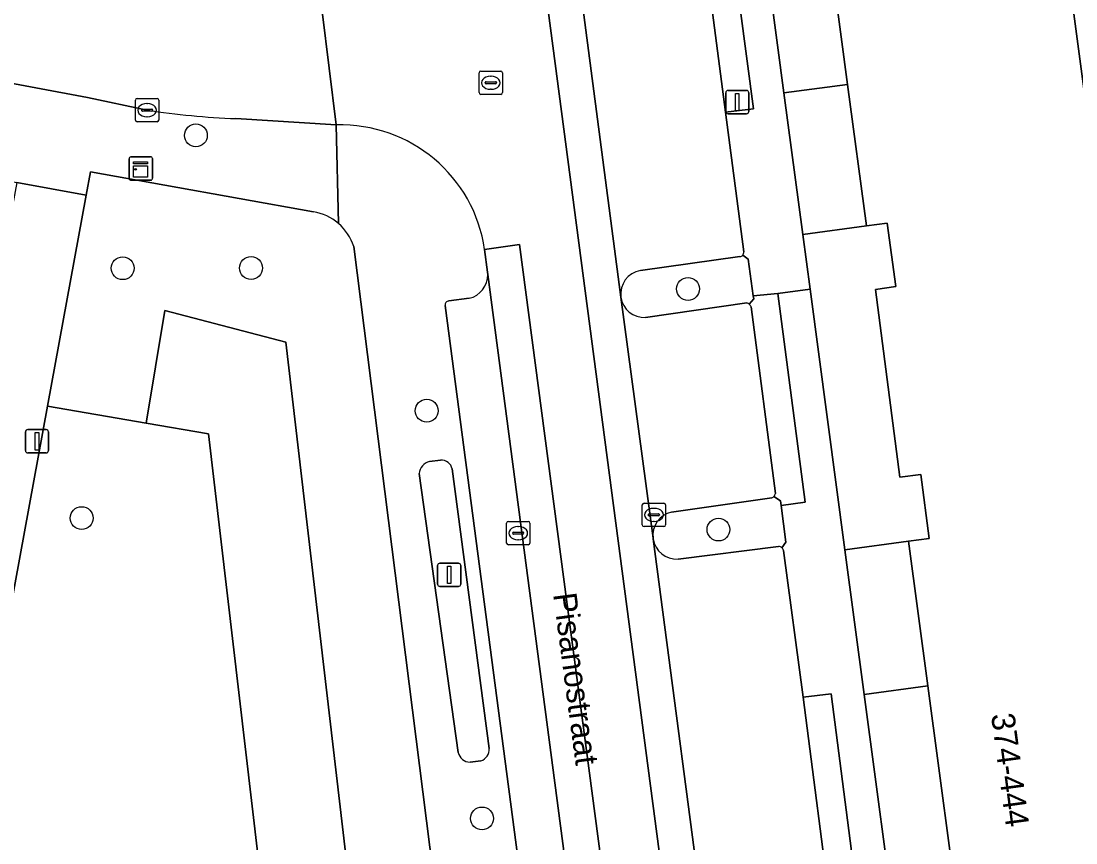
# Model space of a CAD drawing. Extents: x 160554 to 161248, y 385329 to 386506.
# Drawn here: x 161065.87 to 161111.05, y 385894.19 to 385929.39 of the extents above; entities that cross this region are included whole.
import ezdxf

# ---------------------------------------------------------------- set-up
doc = ezdxf.new("R2010")
doc.units = 0
for name, color, linetype in [('IMGEO_Boom', 7, 'Continuous'), ('IMGEO_Groenvoorziening', 7, 'Continuous'), ('IMGEO_Haag', 7, 'Continuous'), ('IMGEO_Kast', 7, 'Continuous'), ('IMGEO_Kolk', 7, 'Continuous'), ('IMGEO_Lichtmast', 7, 'Continuous'), ('IMGEO_Openbare_ruimte_label', 7, 'Continuous'), ('IMGEO_Pand', 7, 'Continuous'), ('IMGEO_Pand_nummerreeks', 7, 'Continuous'), ('IMGEO_Parkeervlak_open', 7, 'Continuous'), ('IMGEO_Rijbaan_lokaal_gesloten', 7, 'Continuous'), ('IMGEO_Rijbaan_lokaal_open', 7, 'Continuous'), ('IMGEO_Rioolput', 7, 'Continuous'), ('IMGEO_Voetpad_open', 7, 'Continuous')]:
    doc.layers.add(name, color=color, linetype=linetype)

msp = doc.modelspace()

# ---------------------------------------------------------------- linework, layer by layer
at = {"layer": 'IMGEO_Boom'}
for centre in [(161073.358, 385924.495), (161070.224, 385918.805), (161075.721, 385918.814), (161094.439, 385917.918), (161083.247, 385912.7), (161068.466, 385908.101), (161095.744, 385907.61), (161085.615, 385895.235)]:
    msp.add_circle(centre, 0.489, dxfattribs=at)
at = {"layer": 'IMGEO_Groenvoorziening'}
for points in [[(161098.548, 385926.313), (161099.356, 385920.254), (161102.083, 385920.618), (161101.275, 385926.677)], [(161079.757, 385878.995), (161080.853, 385884.49), (161077.206, 385915.641), (161072.024, 385916.988), (161071.224, 385912.172), (161073.9, 385911.717), (161077.071, 385884.684), (161075.036, 385880.979), (161079.44, 385879.028)], [(161101.158, 385906.745), (161101.984, 385900.55), (161104.711, 385900.914), (161103.885, 385907.108)]]:
    msp.add_lwpolyline(points, close=True, dxfattribs=at)
for points in [[(161078.39, 385921.217), (161068.84, 385922.94), (161068.656, 385921.934), (161067, 385912.891), (161071.224, 385912.172), (161072.024, 385916.988), (161077.206, 385915.641), (161080.853, 385884.49), (161079.757, 385878.995), (161081.825, 385878.782), (161085.275, 385879.091), (161085.004, 385881.132), (161080.12, 385919.735)], [(161096.664, 385919.302), (161092.398, 385918.707)], [(161097.057, 385917.265), (161097.256, 385917.492), (161097.237, 385917.622), (161097.009, 385919.191), (161096.784, 385919.367)], [(161092.623, 385916.697), (161096.955, 385917.319)], [(161073.9, 385911.717), (161071.224, 385912.172), (161067, 385912.891), (161058.528, 385866.63), (161058.312, 385865.35)], [(161086.501, 385869.656), (161086.193, 385872.192), (161085.275, 385879.091), (161081.825, 385878.782), (161079.757, 385878.995), (161079.44, 385879.028), (161075.036, 385880.979), (161077.071, 385884.684), (161073.9, 385911.717)], [(161083.842, 385910.589), (161083.366, 385910.52)], [(161085.921, 385898.228), (161084.342, 385910.204)], [(161082.922, 385910.009), (161084.595, 385898.064)], [(161098.031, 385908.963), (161093.738, 385908.356)], [(161098.427, 385908.647), (161098.403, 385908.839), (161098.122, 385909.031)], [(161098.463, 385906.833), (161098.628, 385907.063), (161098.427, 385908.647)], [(161092.941, 385907.237), (161092.944, 385907.216)], [(161094.014, 385906.347), (161098.315, 385906.888)], [(161085.103, 385897.643), (161085.566, 385897.703)]]:
    msp.add_lwpolyline(points, dxfattribs=at)
for centre, radius, start, end in [((161078.046, 385919.066), 2.179, 49.4084, 80.9263), ((161078.045, 385919.064), 2.181, 17.9184, 49.408), ((161096.642, 385919.487), 0.186, 276.9194, 319.9665), ((161092.59, 385917.687), 1.038, 100.6546, 186.6899), ((161092.561, 385917.706), 1.011, 187.9847, 273.5363), ((161096.874, 385917.042), 0.289, 50.579, 73.6265), ((161083.513, 385909.944), 0.595, 104.3435, 173.6827), ((161083.85, 385910.082), 0.507, 13.9246, 90.8829), ((161097.92, 385909.206), 0.267, 294.5087, 319.0293), ((161093.951, 385907.361), 1.018, 102.0884, 186.9914), ((161093.958, 385907.371), 1.025, 188.6804, 273.1561), ((161098.321, 385906.677), 0.211, 47.6298, 91.5979), ((161085.113, 385898.172), 0.529, 191.7526, 268.9476), ((161085.405, 385898.194), 0.517, 288.1091, 3.7585)]:
    msp.add_arc(centre, radius, start, end, dxfattribs=at)
at = {"layer": 'IMGEO_Haag'}
for points in [[(161098.548, 385926.313), (161099.356, 385920.254), (161102.083, 385920.618), (161101.275, 385926.677)], [(161101.158, 385906.745), (161101.984, 385900.55), (161104.711, 385900.914), (161103.885, 385907.108)]]:
    msp.add_lwpolyline(points, close=True, dxfattribs=at)
at = {"layer": 'IMGEO_Kast'}
for p, q in [((161070.498, 385922.651), (161070.498, 385923.492)), ((161070.498, 385923.492), (161070.498, 385922.651)), ((161070.573, 385923.576), (161071.414, 385923.576)), ((161071.414, 385923.576), (161070.573, 385923.576)), ((161071.498, 385923.501), (161071.498, 385922.66)), ((161071.498, 385922.66), (161071.498, 385923.501)), ((161071.423, 385922.576), (161070.582, 385922.576)), ((161070.582, 385922.576), (161071.423, 385922.576))]:
    msp.add_line(p, q, dxfattribs=at)
for points in [[(161070.693, 385923.366), (161071.293, 385923.366), (161071.293, 385923.281), (161070.693, 385923.281), (161070.693, 385923.366)], [(161070.693, 385923.191), (161071.293, 385923.191), (161071.293, 385922.702), (161070.693, 385922.702), (161070.693, 385923.191)]]:
    msp.add_lwpolyline(points, dxfattribs=at)
msp.add_circle((161070.777, 385923.04), 0.0377, dxfattribs=at)
for centre, start, end in [((161070.576, 385923.498), 92.4484, 184.2845), ((161070.576, 385923.498), 92.4484, 184.2845), ((161071.42, 385923.498), 2.4484, 94.2845), ((161071.42, 385923.498), 2.4484, 94.2845), ((161070.576, 385922.654), 182.4484, 274.2845), ((161070.576, 385922.654), 182.4484, 274.2845), ((161071.42, 385922.654), 272.4484, 4.2845), ((161071.42, 385922.654), 272.4484, 4.2845)]:
    msp.add_arc(centre, 0.0779, start, end, dxfattribs=at)
at = {"layer": 'IMGEO_Kolk'}
for p, q in [((161070.767, 385925.151), (161070.767, 385926.003)), ((161070.842, 385926.077), (161071.694, 385926.077)), ((161071.768, 385926.003), (161071.768, 385925.151)), ((161071.026, 385925.571), (161071.026, 385925.583)), ((161071.464, 385925.534), (161071.066, 385925.534)), ((161071.069, 385925.62), (161071.467, 385925.62)), ((161071.255, 385925.857), (161071.28, 385925.857)), ((161071.51, 385925.583), (161071.51, 385925.571)), ((161071.694, 385925.077), (161070.842, 385925.077)), ((161071.278, 385925.297), (161071.253, 385925.297)), ((161092.555, 385908.739), (161093.407, 385908.739)), ((161092.48, 385907.813), (161092.48, 385908.665)), ((161092.782, 385908.282), (161093.18, 385908.282)), ((161092.968, 385908.519), (161092.993, 385908.519)), ((161093.481, 385908.665), (161093.481, 385907.813)), ((161086.668, 385907.03), (161086.668, 385907.882)), ((161086.743, 385907.956), (161087.595, 385907.956)), ((161087.669, 385907.882), (161087.669, 385907.03)), ((161092.739, 385908.233), (161092.739, 385908.245)), ((161093.177, 385908.196), (161092.779, 385908.196)), ((161092.991, 385907.959), (161092.966, 385907.959)), ((161093.223, 385908.245), (161093.223, 385908.233)), ((161086.927, 385907.45), (161086.927, 385907.462)), ((161087.365, 385907.413), (161086.967, 385907.413)), ((161086.97, 385907.499), (161087.368, 385907.499)), ((161087.156, 385907.736), (161087.181, 385907.736)), ((161087.411, 385907.462), (161087.411, 385907.45)), ((161093.407, 385907.739), (161092.555, 385907.739)), ((161087.595, 385906.956), (161086.743, 385906.956)), ((161087.179, 385907.176), (161087.154, 385907.176))]:
    msp.add_line(p, q, dxfattribs=at)
for points in [[(161070.767, 385925.151), (161070.767, 385926.003)], [(161070.842, 385926.077), (161071.694, 385926.077)], [(161071.768, 385926.003), (161071.768, 385925.151)], [(161071.694, 385925.077), (161070.842, 385925.077)], [(161092.555, 385908.739), (161093.407, 385908.739)], [(161092.48, 385907.813), (161092.48, 385908.665)], [(161093.481, 385908.665), (161093.481, 385907.813)], [(161086.668, 385907.03), (161086.668, 385907.882)], [(161086.743, 385907.956), (161087.595, 385907.956)], [(161087.669, 385907.882), (161087.669, 385907.03)], [(161093.407, 385907.739), (161092.555, 385907.739)], [(161087.595, 385906.956), (161086.743, 385906.956)]]:
    msp.add_lwpolyline(points, dxfattribs=at)
for centre, radius, start, end in [((161070.844, 385926.001), 0.0765, 91.552, 178.448), ((161070.844, 385926.001), 0.0765, 91.552, 178.448), ((161071.692, 385926.001), 0.0765, 1.552, 88.448), ((161071.692, 385926.001), 0.0765, 1.552, 88.448), ((161071.066, 385925.58), 0.0403, 85.8775, 175.7526), ((161071.063, 385925.57), 0.0366, 178.938, 274.7102), ((161071.467, 385925.577), 0.043, 264.8664, 352.4533), ((161071.471, 385925.582), 0.0386, 1.7309, 96.639), ((161070.844, 385925.153), 0.0765, 181.552, 268.448), ((161070.844, 385925.153), 0.0765, 181.552, 268.448), ((161071.692, 385925.153), 0.0765, 271.552, 358.448), ((161071.692, 385925.153), 0.0765, 271.552, 358.448), ((161092.557, 385908.663), 0.0765, 91.552, 178.448), ((161092.557, 385908.663), 0.0765, 91.552, 178.448), ((161093.405, 385908.663), 0.0765, 1.552, 88.448), ((161093.405, 385908.663), 0.0765, 1.552, 88.448), ((161092.779, 385908.242), 0.0403, 85.8775, 175.7526), ((161093.184, 385908.244), 0.0386, 1.7309, 96.639), ((161086.745, 385907.88), 0.0765, 91.552, 178.448), ((161086.745, 385907.88), 0.0765, 91.552, 178.448), ((161087.593, 385907.88), 0.0765, 1.552, 88.448), ((161087.593, 385907.88), 0.0765, 1.552, 88.448), ((161092.557, 385907.815), 0.0765, 181.552, 268.448), ((161092.557, 385907.815), 0.0765, 181.552, 268.448), ((161092.776, 385908.232), 0.0366, 178.938, 274.7102), ((161093.18, 385908.239), 0.043, 264.8664, 352.4533), ((161093.405, 385907.815), 0.0765, 271.552, 358.448), ((161093.405, 385907.815), 0.0765, 271.552, 358.448), ((161086.967, 385907.459), 0.0403, 85.8775, 175.7526), ((161086.964, 385907.449), 0.0366, 178.938, 274.7102), ((161087.368, 385907.456), 0.043, 264.8664, 352.4533), ((161087.372, 385907.461), 0.0386, 1.7309, 96.639), ((161086.745, 385907.032), 0.0765, 181.552, 268.448), ((161086.745, 385907.032), 0.0765, 181.552, 268.448), ((161087.593, 385907.032), 0.0765, 271.552, 358.448), ((161087.593, 385907.032), 0.0765, 271.552, 358.448)]:
    msp.add_arc(centre, radius, start, end, dxfattribs=at)
for centre, major_axis, ratio, start_param, end_param in [((161071.254, 385925.577), (-0.387, 0.002), 0.722429, 4.712389, 7.853982), ((161071.279, 385925.577), (-0.39, 0.002), 0.717154, 1.570796, 4.712389), ((161092.967, 385908.239), (-0.387, 0.002), 0.722429, 4.712389, 7.853982), ((161092.992, 385908.239), (-0.39, 0.002), 0.717154, 1.570796, 4.712389), ((161087.155, 385907.456), (-0.387, 0.002), 0.722429, 4.712389, 7.853982), ((161087.18, 385907.456), (-0.39, 0.002), 0.717154, 1.570796, 4.712389)]:
    msp.add_ellipse(centre, major_axis=major_axis, ratio=ratio, start_param=start_param, end_param=end_param, dxfattribs=at)
at = {"layer": 'IMGEO_Lichtmast'}
for p, q in [((161096.153, 385926.421), (161096.943, 385926.421)), ((161096.943, 385926.421), (161096.153, 385926.421)), ((161096.053, 385925.521), (161096.053, 385926.321)), ((161096.053, 385926.321), (161096.053, 385925.521)), ((161097.043, 385926.321), (161097.043, 385925.521)), ((161097.043, 385925.521), (161097.043, 385926.321)), ((161096.943, 385925.421), (161096.153, 385925.421)), ((161096.153, 385925.421), (161096.943, 385925.421)), ((161066.156, 385911.892), (161066.946, 385911.892)), ((161066.946, 385911.892), (161066.156, 385911.892)), ((161066.056, 385910.992), (161066.056, 385911.792)), ((161066.056, 385911.792), (161066.056, 385910.992)), ((161067.046, 385911.792), (161067.046, 385910.992)), ((161067.046, 385910.992), (161067.046, 385911.792)), ((161066.946, 385910.892), (161066.156, 385910.892)), ((161066.156, 385910.892), (161066.946, 385910.892)), ((161083.712, 385905.27), (161083.712, 385906.07)), ((161083.712, 385906.07), (161083.712, 385905.27)), ((161083.812, 385906.17), (161084.602, 385906.17)), ((161084.602, 385906.17), (161083.812, 385906.17)), ((161084.702, 385906.07), (161084.702, 385905.27)), ((161084.702, 385905.27), (161084.702, 385906.07)), ((161084.602, 385905.17), (161083.812, 385905.17)), ((161083.812, 385905.17), (161084.602, 385905.17))]:
    msp.add_line(p, q, dxfattribs=at)
for points in [[(161096.473, 385926.296), (161096.623, 385926.296), (161096.623, 385925.546), (161096.473, 385925.546), (161096.473, 385926.296)], [(161066.476, 385911.767), (161066.626, 385911.767), (161066.626, 385911.017), (161066.476, 385911.017), (161066.476, 385911.767)], [(161084.132, 385906.045), (161084.282, 385906.045), (161084.282, 385905.295), (161084.132, 385905.295), (161084.132, 385906.045)]]:
    msp.add_lwpolyline(points, dxfattribs=at)
for centre, start, end in [((161096.153, 385926.321), 90, 180), ((161096.153, 385926.321), 90, 180), ((161096.943, 385926.321), 0, 90), ((161096.943, 385926.321), 360, 90), ((161096.153, 385925.521), 180, 270), ((161096.153, 385925.521), 180, 270), ((161096.943, 385925.521), 270, 0), ((161096.943, 385925.521), 270, 0), ((161066.156, 385911.792), 90, 180), ((161066.156, 385911.792), 90, 180), ((161066.946, 385911.792), 0, 90), ((161066.946, 385911.792), 360, 90), ((161066.156, 385910.992), 180, 270), ((161066.156, 385910.992), 180, 270), ((161066.946, 385910.992), 270, 0), ((161066.946, 385910.992), 270, 0), ((161083.812, 385906.07), 90, 180), ((161083.812, 385906.07), 90, 180), ((161084.602, 385906.07), 0, 90), ((161084.602, 385906.07), 360, 90), ((161083.812, 385905.27), 180, 270), ((161083.812, 385905.27), 180, 270), ((161084.602, 385905.27), 270, 0), ((161084.602, 385905.27), 270, 0)]:
    msp.add_arc(centre, 0.1, start, end, dxfattribs=at)
at = {"layer": 'IMGEO_Pand'}
for points in [[(161122.665, 385842.019), (161108.009, 385951.88)], [(161099.853, 385937.33), (161101.275, 385926.677), (161102.083, 385920.618), (161102.974, 385920.737), (161103.337, 385918.015), (161102.464, 385917.898), (161103.519, 385909.85), (161104.41, 385909.969), (161104.776, 385907.227), (161103.885, 385907.108), (161104.711, 385900.914), (161106.152, 385890.116), (161106.955, 385884.097), (161107.846, 385884.216), (161108.209, 385881.494), (161107.318, 385881.375), (161108.383, 385873.388), (161109.274, 385873.507), (161109.637, 385870.785)]]:
    msp.add_lwpolyline(points, dxfattribs=at)
at = {"layer": 'IMGEO_Parkeervlak_open'}
for points in [[(161088.129, 385943.731), (161091.559, 385917.566)], [(161096.829, 385919.511), (161096.047, 385925.489), (161094.628, 385936.338)], [(161092.398, 385918.707), (161096.664, 385919.302)], [(161091.601, 385874.985), (161085.861, 385918.538)], [(161085.06, 385917.516), (161084.195, 385917.403)], [(161091.559, 385917.566), (161092.941, 385907.237)], [(161096.955, 385917.319), (161092.623, 385916.697)], [(161084.034, 385917.203), (161089.495, 385875.772)], [(161098.183, 385909.158), (161097.143, 385917.154)], [(161093.738, 385908.356), (161098.031, 385908.963)], [(161092.944, 385907.216), (161095.353, 385888.901)], [(161098.315, 385906.888), (161094.014, 385906.347)], [(161100.62, 385890.798), (161099.365, 385900.431), (161098.527, 385906.718)]]:
    msp.add_lwpolyline(points, dxfattribs=at)
for centre, radius, start, end in [((161096.642, 385919.487), 0.186, 276.9194, 319.9665), ((161096.637, 385919.492), 0.193, 319.6683, 5.6236), ((161092.59, 385917.687), 1.038, 100.6546, 186.6899), ((161084.831, 385918.521), 1.031, 282.8629, 0.9614), ((161084.202, 385917.232), 0.171, 92.4059, 189.926), ((161092.561, 385917.706), 1.011, 187.9847, 273.5363), ((161096.874, 385917.042), 0.289, 50.579, 73.6265), ((161096.885, 385917.043), 0.281, 23.3152, 52.22), ((161097.92, 385909.206), 0.267, 294.5087, 319.0293), ((161097.924, 385909.204), 0.263, 318.8069, 349.8818), ((161093.951, 385907.361), 1.018, 102.0884, 186.9914), ((161093.958, 385907.371), 1.025, 188.6804, 273.1561), ((161098.321, 385906.677), 0.211, 47.6298, 91.5979), ((161098.32, 385906.678), 0.211, 10.8986, 47.2952)]:
    msp.add_arc(centre, radius, start, end, dxfattribs=at)
at = {"layer": 'IMGEO_Rijbaan_lokaal_gesloten'}
for points in [[(161079.588, 386008.613), (161079.58, 386008.672), (161078.134, 386008.45), (161086.055, 385948.036), (161095.806, 385874.121), (161097.248, 385874.322), (161096.551, 385879.856), (161095.45, 385888.19), (161095.353, 385888.901), (161092.944, 385907.216), (161092.941, 385907.237), (161091.559, 385917.566), (161088.129, 385943.731)], [(161091.626, 385874.859), (161091.801, 385873.54), (161093.321, 385873.775), (161087.218, 385919.823), (161085.726, 385919.607)], [(161085.726, 385919.607), (161085.855, 385918.638), (161085.861, 385918.538), (161091.601, 385874.985)]]:
    msp.add_lwpolyline(points, dxfattribs=at)
at = {"layer": 'IMGEO_Rijbaan_lokaal_open'}
for points in [[(161085.726, 385919.607), (161087.218, 385919.823), (161093.321, 385873.775), (161095.806, 385874.121), (161086.055, 385948.036)], [(161016.089, 385935.913), (161064.497, 385926.9), (161068.716, 385926.115), (161071.268, 385925.577)], [(161075.073, 385925.216), (161079.374, 385924.941), (161078.764, 385929.805)], [(161078.764, 385929.805), (161079.374, 385924.941)]]:
    msp.add_lwpolyline(points, dxfattribs=at)
for points in [[(161097.126, 385936.966), (161098.548, 385926.313), (161101.275, 385926.677), (161099.853, 385937.33)], [(161102.464, 385917.898), (161103.337, 385918.015), (161102.974, 385920.737), (161102.083, 385920.618), (161099.356, 385920.254), (161099.668, 385917.914), (161101.158, 385906.745), (161103.885, 385907.108), (161104.776, 385907.227), (161104.41, 385909.969), (161103.519, 385909.85)], [(161103.425, 385889.752), (161106.152, 385890.116), (161104.711, 385900.914), (161101.984, 385900.55)]]:
    msp.add_lwpolyline(points, close=True, dxfattribs=at)
for centre, radius, start, end in [((161076.25, 385957.853), 32.658, 261.2256, 267.935), ((161079.564, 385918.718), 6.226, 8.2094, 91.7478)]:
    msp.add_arc(centre, radius, start, end, dxfattribs=at)
at = {"layer": 'IMGEO_Rioolput'}
for p, q in [((161085.566, 385927.252), (161086.418, 385927.252)), ((161085.491, 385926.326), (161085.491, 385927.178)), ((161085.793, 385926.795), (161086.191, 385926.795)), ((161085.979, 385927.032), (161086.004, 385927.032)), ((161086.492, 385927.178), (161086.492, 385926.326)), ((161085.75, 385926.746), (161085.75, 385926.758)), ((161086.188, 385926.709), (161085.79, 385926.709)), ((161086.002, 385926.472), (161085.977, 385926.472)), ((161086.234, 385926.758), (161086.234, 385926.746)), ((161086.418, 385926.252), (161085.566, 385926.252))]:
    msp.add_line(p, q, dxfattribs=at)
for points in [[(161085.566, 385927.252), (161086.418, 385927.252)], [(161085.491, 385926.326), (161085.491, 385927.178)], [(161086.492, 385927.178), (161086.492, 385926.326)], [(161086.418, 385926.252), (161085.566, 385926.252)]]:
    msp.add_lwpolyline(points, dxfattribs=at)
for centre, radius, start, end in [((161085.568, 385927.176), 0.0765, 91.552, 178.448), ((161085.568, 385927.176), 0.0765, 91.552, 178.448), ((161086.416, 385927.176), 0.0765, 1.552, 88.448), ((161086.416, 385927.176), 0.0765, 1.552, 88.448), ((161085.79, 385926.755), 0.0403, 85.8775, 175.7526), ((161086.195, 385926.757), 0.0386, 1.7309, 96.639), ((161085.787, 385926.745), 0.0366, 178.938, 274.7102), ((161086.191, 385926.752), 0.043, 264.8664, 352.4533), ((161085.568, 385926.328), 0.0765, 181.552, 268.448), ((161085.568, 385926.328), 0.0765, 181.552, 268.448), ((161086.416, 385926.328), 0.0765, 271.552, 358.448), ((161086.416, 385926.328), 0.0765, 271.552, 358.448)]:
    msp.add_arc(centre, radius, start, end, dxfattribs=at)
for centre, major_axis, ratio, start_param, end_param in [((161085.978, 385926.752), (-0.387, 0.002), 0.722429, 4.712389, 7.853982), ((161086.003, 385926.752), (-0.39, 0.002), 0.717154, 1.570796, 4.712389)]:
    msp.add_ellipse(centre, major_axis=major_axis, ratio=ratio, start_param=start_param, end_param=end_param, dxfattribs=at)
at = {"layer": 'IMGEO_Voetpad_open'}
for points in [[(161096.784, 385919.367), (161097.009, 385919.191), (161097.237, 385917.622), (161098.284, 385917.719), (161099.668, 385917.914), (161099.356, 385920.254), (161098.548, 385926.313), (161097.126, 385936.966), (161096.292, 385943.217), (161095.494, 385949.098), (161094.874, 385953.891), (161093.966, 385960.914), (161093.633, 385962.998), (161088.666, 386000), (161082.13, 386049.396)], [(161093.693, 385943.45), (161094.611, 385936.475), (161094.628, 385936.338), (161095.797, 385936.505), (161097.239, 385925.634), (161096.047, 385925.489), (161096.829, 385919.511)], [(161013.833, 385932.134), (161039.687, 385927.317), (161041.117, 385927.05), (161044.828, 385926.359), (161059.378, 385923.648), (161065.687, 385922.472), (161068.656, 385921.934), (161068.84, 385922.94), (161078.39, 385921.217)], [(161071.268, 385925.577), (161068.716, 385926.115), (161064.497, 385926.9)], [(161079.374, 385924.941), (161075.073, 385925.216)], [(161079.464, 385920.72), (161079.374, 385924.941)], [(161079.374, 385924.941), (161079.464, 385920.72)], [(161058.312, 385865.35), (161058.528, 385866.63), (161067, 385912.891), (161068.656, 385921.934), (161065.687, 385922.472), (161055.411, 385866.741), (161054.477, 385866.855)], [(161080.12, 385919.735), (161085.004, 385881.132), (161085.275, 385879.091), (161086.193, 385872.192), (161086.501, 385869.656)], [(161085.861, 385918.538), (161085.855, 385918.638), (161085.726, 385919.607)], [(161107.835, 385833.357), (161110.155, 385838.705), (161109.707, 385841.529), (161109.093, 385847.254), (161108.31, 385853.127), (161106.831, 385864.213), (161106.018, 385870.302), (161105.071, 385877.411), (161104.228, 385883.733), (161103.425, 385889.752), (161101.984, 385900.55), (161101.158, 385906.745), (161099.668, 385917.914), (161098.284, 385917.719), (161099.453, 385908.779), (161098.427, 385908.647), (161098.628, 385907.063), (161098.463, 385906.833)], [(161084.195, 385917.403), (161085.06, 385917.516)], [(161097.237, 385917.622), (161097.256, 385917.492), (161097.057, 385917.265)], [(161098.122, 385909.031), (161098.403, 385908.839), (161098.427, 385908.647), (161099.453, 385908.779), (161098.284, 385917.719), (161097.237, 385917.622)], [(161089.495, 385875.772), (161084.034, 385917.203)], [(161097.143, 385917.154), (161098.183, 385909.158)], [(161083.366, 385910.52), (161083.842, 385910.589)], [(161084.342, 385910.204), (161085.921, 385898.228)], [(161084.595, 385898.064), (161082.922, 385910.009)], [(161098.527, 385906.718), (161099.365, 385900.431), (161100.569, 385900.576), (161101.817, 385890.96), (161100.62, 385890.798)], [(161085.566, 385897.703), (161085.103, 385897.643)]]:
    msp.add_lwpolyline(points, dxfattribs=at)
for points in [[(161097.601, 385954.29), (161098.088, 385950.557), (161108.009, 385951.88), (161122.665, 385842.019), (161123.708, 385842.158), (161122.752, 385849.325), (161121.251, 385860.582), (161118.463, 385881.489), (161115.749, 385901.843), (161112.775, 385924.141), (161109.928, 385945.494), (161108.541, 385955.891)], [(161094.628, 385936.338), (161096.047, 385925.489), (161097.239, 385925.634), (161095.797, 385936.505)], [(161099.365, 385900.431), (161100.62, 385890.798), (161101.817, 385890.96), (161100.569, 385900.576)]]:
    msp.add_lwpolyline(points, close=True, dxfattribs=at)
for centre, radius, start, end in [((161076.25, 385957.853), 32.658, 261.2256, 267.935), ((161079.564, 385918.718), 6.226, 8.2094, 91.7478), ((161078.046, 385919.066), 2.179, 49.4084, 80.9263), ((161078.045, 385919.064), 2.181, 17.9184, 49.408), ((161096.637, 385919.492), 0.193, 319.6683, 5.6236), ((161084.831, 385918.521), 1.031, 282.8629, 0.9614), ((161084.202, 385917.232), 0.171, 92.4059, 189.926), ((161096.885, 385917.043), 0.281, 23.3152, 52.22), ((161083.513, 385909.944), 0.595, 104.3435, 173.6827), ((161083.85, 385910.082), 0.507, 13.9246, 90.8829), ((161097.924, 385909.204), 0.263, 318.8069, 349.8818), ((161098.32, 385906.678), 0.211, 10.8986, 47.2952), ((161085.113, 385898.172), 0.529, 191.7526, 268.9476), ((161085.405, 385898.194), 0.517, 288.1091, 3.7585)]:
    msp.add_arc(centre, radius, start, end, dxfattribs=at)

# ---------------------------------------------------------------- texts
at = {"layer": 'IMGEO_Openbare_ruimte_label'}
msp.add_text('Pisanostraat', height=1, rotation=277.5303, dxfattribs=at).set_placement((161088.659, 385904.841))
at = {"layer": 'IMGEO_Pand_nummerreeks'}
msp.add_text('374-444', height=1, rotation=277.5992, dxfattribs=at).set_placement((161107.418, 385899.683))

doc.saveas('drawing.dxf')
